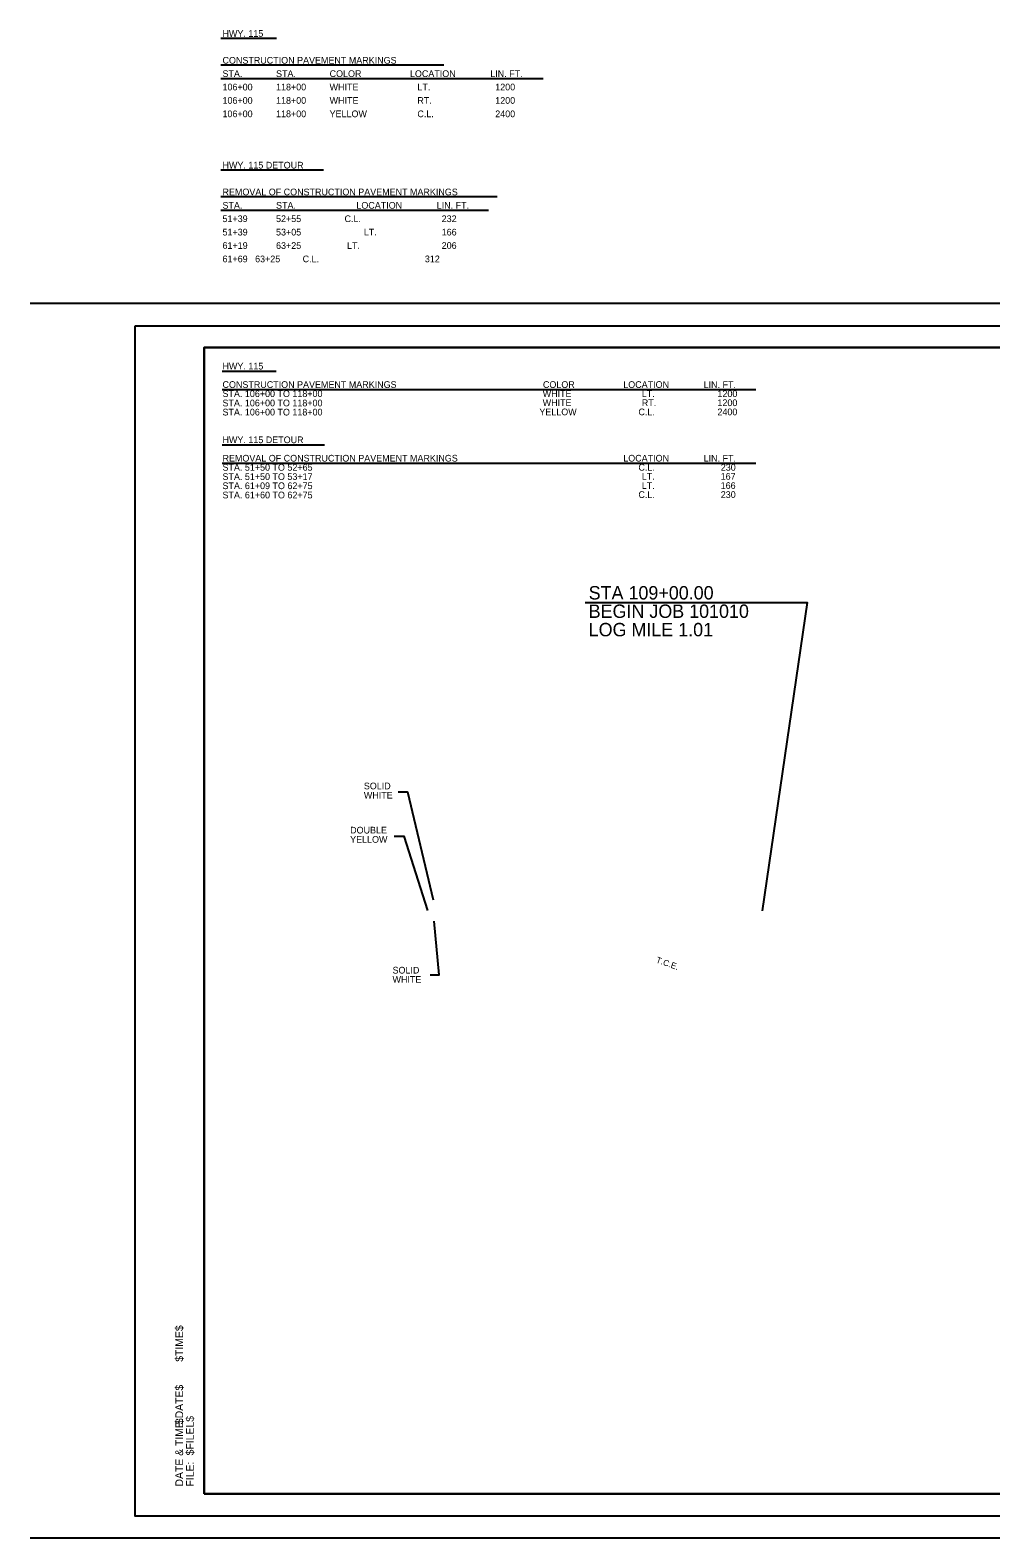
# Model space of a CAD drawing. Extents: x 9844 to 11605, y 9961 to 11312.
# Drawn here: x 9844 to 10705, y 9961 to 11312 of the extents above; entities that cross this region are included whole.
import ezdxf

# ---------------------------------------------------------------- set-up
doc = ezdxf.new("R2010")
doc.units = 0
for name, color, linetype in [('GREEN_TXT', 7, 'Continuous'), ('R_Erosion', 7, 'Continuous'), ('R_Temp Const Easement Annot', 7, 'Continuous'), ('SEAL-INFO', 7, 'Continuous'), ('STA Text', 7, 'Continuous'), ('Stage 2', 7, 'Continuous'), ('TEXT', 7, 'Continuous')]:
    doc.layers.add(name, color=color, linetype=linetype)

msp = doc.modelspace()

# ---------------------------------------------------------------- linework, layer by layer
at = {"layer": 'GREEN_TXT'}
for p, q in [((11603.9, 11066.7), (9843.9, 11066.7)), ((10000, 11027.3), (11580.9, 11027.3)), ((10000, 10000), (10000, 11027.3)), ((11580.9, 10000), (10000, 10000)), ((9843.9, 9960.6), (11603.9, 9960.6))]:
    msp.add_line(p, q, dxfattribs=at)
at = {"layer": 'R_Erosion'}
for p, q in [((10015.9, 11006.2), (10064.4, 11006.2)), ((10015.9, 10989.7), (10494.2, 10989.7)), ((10015.9, 10940.2), (10107.8, 10940.2)), ((10015.9, 10923.7), (10494.2, 10923.7))]:
    msp.add_line(p, q, dxfattribs=at)
at = {"layer": 'SEAL-INFO'}
for points in [[(9938, 11046.8), (11604.7, 11046.8), (11604.7, 9980.1), (9938, 9980.1)], [(10000, 10000), (11580.9, 10000), (11580.3, 10963.3), (11365.4, 10963.3), (11357.3, 10959.9), (11348.5, 10961.4), (11348.3, 10977.9), (11169.6, 10977.9), (11169.6, 11027.3), (10000, 11027.3)], [(10000, 10000), (11580.9, 10000), (11580.3, 10963.3), (11365.4, 10963.3), (11357.3, 10959.9), (11348.5, 10961.4), (11348.3, 10977.9), (11169.6, 10977.9), (11169.6, 11027.3), (10000, 11027.3)], [(10000, 10000), (11580.9, 10000), (11580.3, 10963.3), (11365.4, 10963.3), (11357.3, 10959.9), (11348.5, 10961.4), (11348.3, 10977.9), (11169.6, 10977.9), (11169.6, 11027.3), (10000, 11027.3)], [(10000, 10000), (11580.9, 10000), (11580.3, 10963.3), (11365.4, 10963.3), (11357.3, 10959.9), (11348.5, 10961.4), (11348.3, 10977.9), (11169.6, 10977.9), (11169.6, 11027.3), (10000, 11027.3)]]:
    msp.add_lwpolyline(points, close=True, dxfattribs=at)
at = {"layer": 'STA Text'}
msp.add_lwpolyline([(10341.5, 10798.7), (10540.4, 10798.7), (10500, 10522.5)], dxfattribs=at)
at = {"layer": 'Stage 2'}
for points in [[(10173.7, 10629), (10182, 10629), (10205.1, 10532.4)], [(10170.3, 10589.3), (10178.7, 10589.3), (10200, 10522.9)], [(10202.3, 10465), (10210.6, 10465), (10206.1, 10513.3)]]:
    msp.add_lwpolyline(points, dxfattribs=at)
at = {"layer": 'TEXT'}
for p, q in [((10014.7, 11304.5), (10064.7, 11304.5)), ((10014.7, 11280.5), (10214.7, 11280.5)), ((10014.7, 11268.5), (10303.7, 11268.5)), ((10014.7, 11186.5), (10106.7, 11186.5)), ((10014.7, 11162.5), (10262.4, 11162.5)), ((10014.7, 11150.5), (10254.7, 11150.5))]:
    msp.add_line(p, q, dxfattribs=at)

# ---------------------------------------------------------------- texts
for s, height, p in [('$TIME$', 6.98, (9981, 10118.4)), ('$DATE$', 6.98, (9981, 10062.5)), ('DATE & TIME:', 6.984, (9981, 10006.6)), ('$FILEL$', 6.98, (9990.6, 10034.5)), ('FILE: ', 6.98, (9990.6, 10006.6))]:
    msp.add_text(s, height=height, rotation=90).set_placement(p)
at = {"layer": 'R_Erosion'}
for s, p in [('HWY. 115', (10016.3, 11007.6)), ('STA. 106+00 TO 118+00', (10016.3, 10982.9)), ('CONSTRUCTION PAVEMENT MARKINGS', (10016.3, 10991.1)), ('WHITE', (10303.3, 10982.9)), ('COLOR', (10303.5, 10991.1)), ('LOCATION', (10375.5, 10991.1)), ('LOCATION', (10375.5, 10991.1)), ('LT.', (10392.1, 10982.9)), ('LIN. FT.', (10447.5, 10991.1)), ('1200', (10459.9, 10982.9)), ('STA. 106+00 TO 118+00', (10016.3, 10974.6)), ('STA. 106+00 TO 118+00', (10016.3, 10966.4)), ('YELLOW', (10300.3, 10966.6)), ('WHITE', (10303.3, 10974.8)), ('C.L.', (10389.1, 10966.6)), ('RT.', (10392.1, 10974.8)), ('2400', (10459.9, 10966.6)), ('1200', (10459.9, 10974.8)), ('HWY. 115 DETOUR', (10016.3, 10941.6)), ('REMOVAL OF CONSTRUCTION PAVEMENT MARKINGS', (10016.3, 10925.1)), ('LOCATION', (10375.5, 10925.1)), ('LOCATION', (10375.5, 10925.1)), ('LIN. FT.', (10447.5, 10925.1)), ('STA. 51+50 TO 52+65', (10016.3, 10916.9)), ('C.L.', (10389.1, 10916.9)), ('230', (10462.9, 10916.9)), ('STA. 51+50 TO 53+17', (10016.3, 10908.6)), ('STA. 61+09 TO 62+75', (10016.3, 10900.4)), ('LT.', (10392.1, 10908.8)), ('LT.', (10392.1, 10900.6)), ('167', (10462.8, 10908.8)), ('166', (10462.8, 10900.6)), ('STA. 61+60 TO 62+75', (10016.3, 10892.1)), ('C.L.', (10389.1, 10892.5)), ('230', (10462.9, 10892.5))]:
    msp.add_text(s, height=6, dxfattribs=at).set_placement(p)
at = {"layer": 'R_Temp Const Easement Annot'}
msp.add_text('T.C.E.', height=5.5, rotation=340.4448, dxfattribs=at).set_placement((10404.4, 10476.3))
at = {"layer": 'STA Text'}
for s, p in [('STA 109+00.00', (10344.5, 10801.5)), ('BEGIN JOB 101010', (10344.5, 10785)), ('LOG MILE 1.01', (10344.5, 10768.5))]:
    msp.add_text(s, height=12, dxfattribs=at).set_placement(p)
at = {"layer": 'Stage 2'}
for s, p in [('SOLID', (10143, 10631.4)), ('WHITE', (10143, 10623.1)), ('DOUBLE', (10130.7, 10591.8)), ('YELLOW', (10130.7, 10583.5)), ('SOLID', (10168.7, 10466.3)), ('WHITE', (10168.7, 10458))]:
    msp.add_text(s, height=6, rotation=360, dxfattribs=at).set_placement(p)
at = {"layer": 'TEXT'}
for s, p in [('HWY. 115 ', (10016.3, 11305.7)), ('CONSTRUCTION PAVEMENT MARKINGS', (10016.3, 11281.7)), ('STA.', (10016.3, 11269.7)), ('STA. ', (10064.3, 11269.7)), ('COLOR', (10112.3, 11269.7)), ('LOCATION', (10184.3, 11269.7)), ('LIN. FT.', (10256.3, 11269.7)), ('106+00', (10016.3, 11257.7)), ('118+00', (10064.3, 11257.7)), ('WHITE', (10112.3, 11257.7)), ('   LT.', (10184.3, 11257.7)), ('  1200', (10256.3, 11257.7)), ('106+00', (10016.3, 11245.7)), ('118+00', (10064.3, 11245.7)), ('WHITE', (10112.3, 11245.7)), ('   RT.', (10184.3, 11245.7)), ('  1200', (10256.3, 11245.7)), ('106+00', (10016.3, 11233.7)), ('118+00', (10064.3, 11233.7)), ('YELLOW', (10112.3, 11233.7)), ('   C.L.', (10184.3, 11233.7)), ('  2400', (10256.3, 11233.7)), ('HWY. 115 DETOUR', (10016.3, 11187.7)), ('REMOVAL OF CONSTRUCTION PAVEMENT MARKINGS', (10016.3, 11163.7)), ('STA.', (10016.3, 11151.7)), ('STA. ', (10064.3, 11151.7)), ('LOCATION', (10136.3, 11151.7)), ('LIN. FT.', (10208.3, 11151.7)), ('51+39', (10016.3, 11139.7)), ('51+39', (10016.3, 11127.7)), ('52+55', (10064.3, 11139.7)), ('53+05', (10064.3, 11127.7)), ('      C.L.', (10112.3, 11139.7)), ('   LT.', (10136.3, 11127.7)), ('  232', (10208.3, 11139.7)), ('  166', (10208.3, 11127.7)), ('61+19', (10016.3, 11115.7)), ('63+25', (10064.3, 11115.7)), ('       LT.', (10112.3, 11115.7)), ('  206', (10208.3, 11115.7)), ('61+69   63+25         C.L.', (10016.3, 11103.7)), ('      312', (10184.3, 11103.7))]:
    msp.add_text(s, height=6, rotation=360, dxfattribs=at).set_placement(p)

doc.saveas('drawing.dxf')
